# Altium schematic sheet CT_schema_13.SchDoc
size 389 x 278 mm
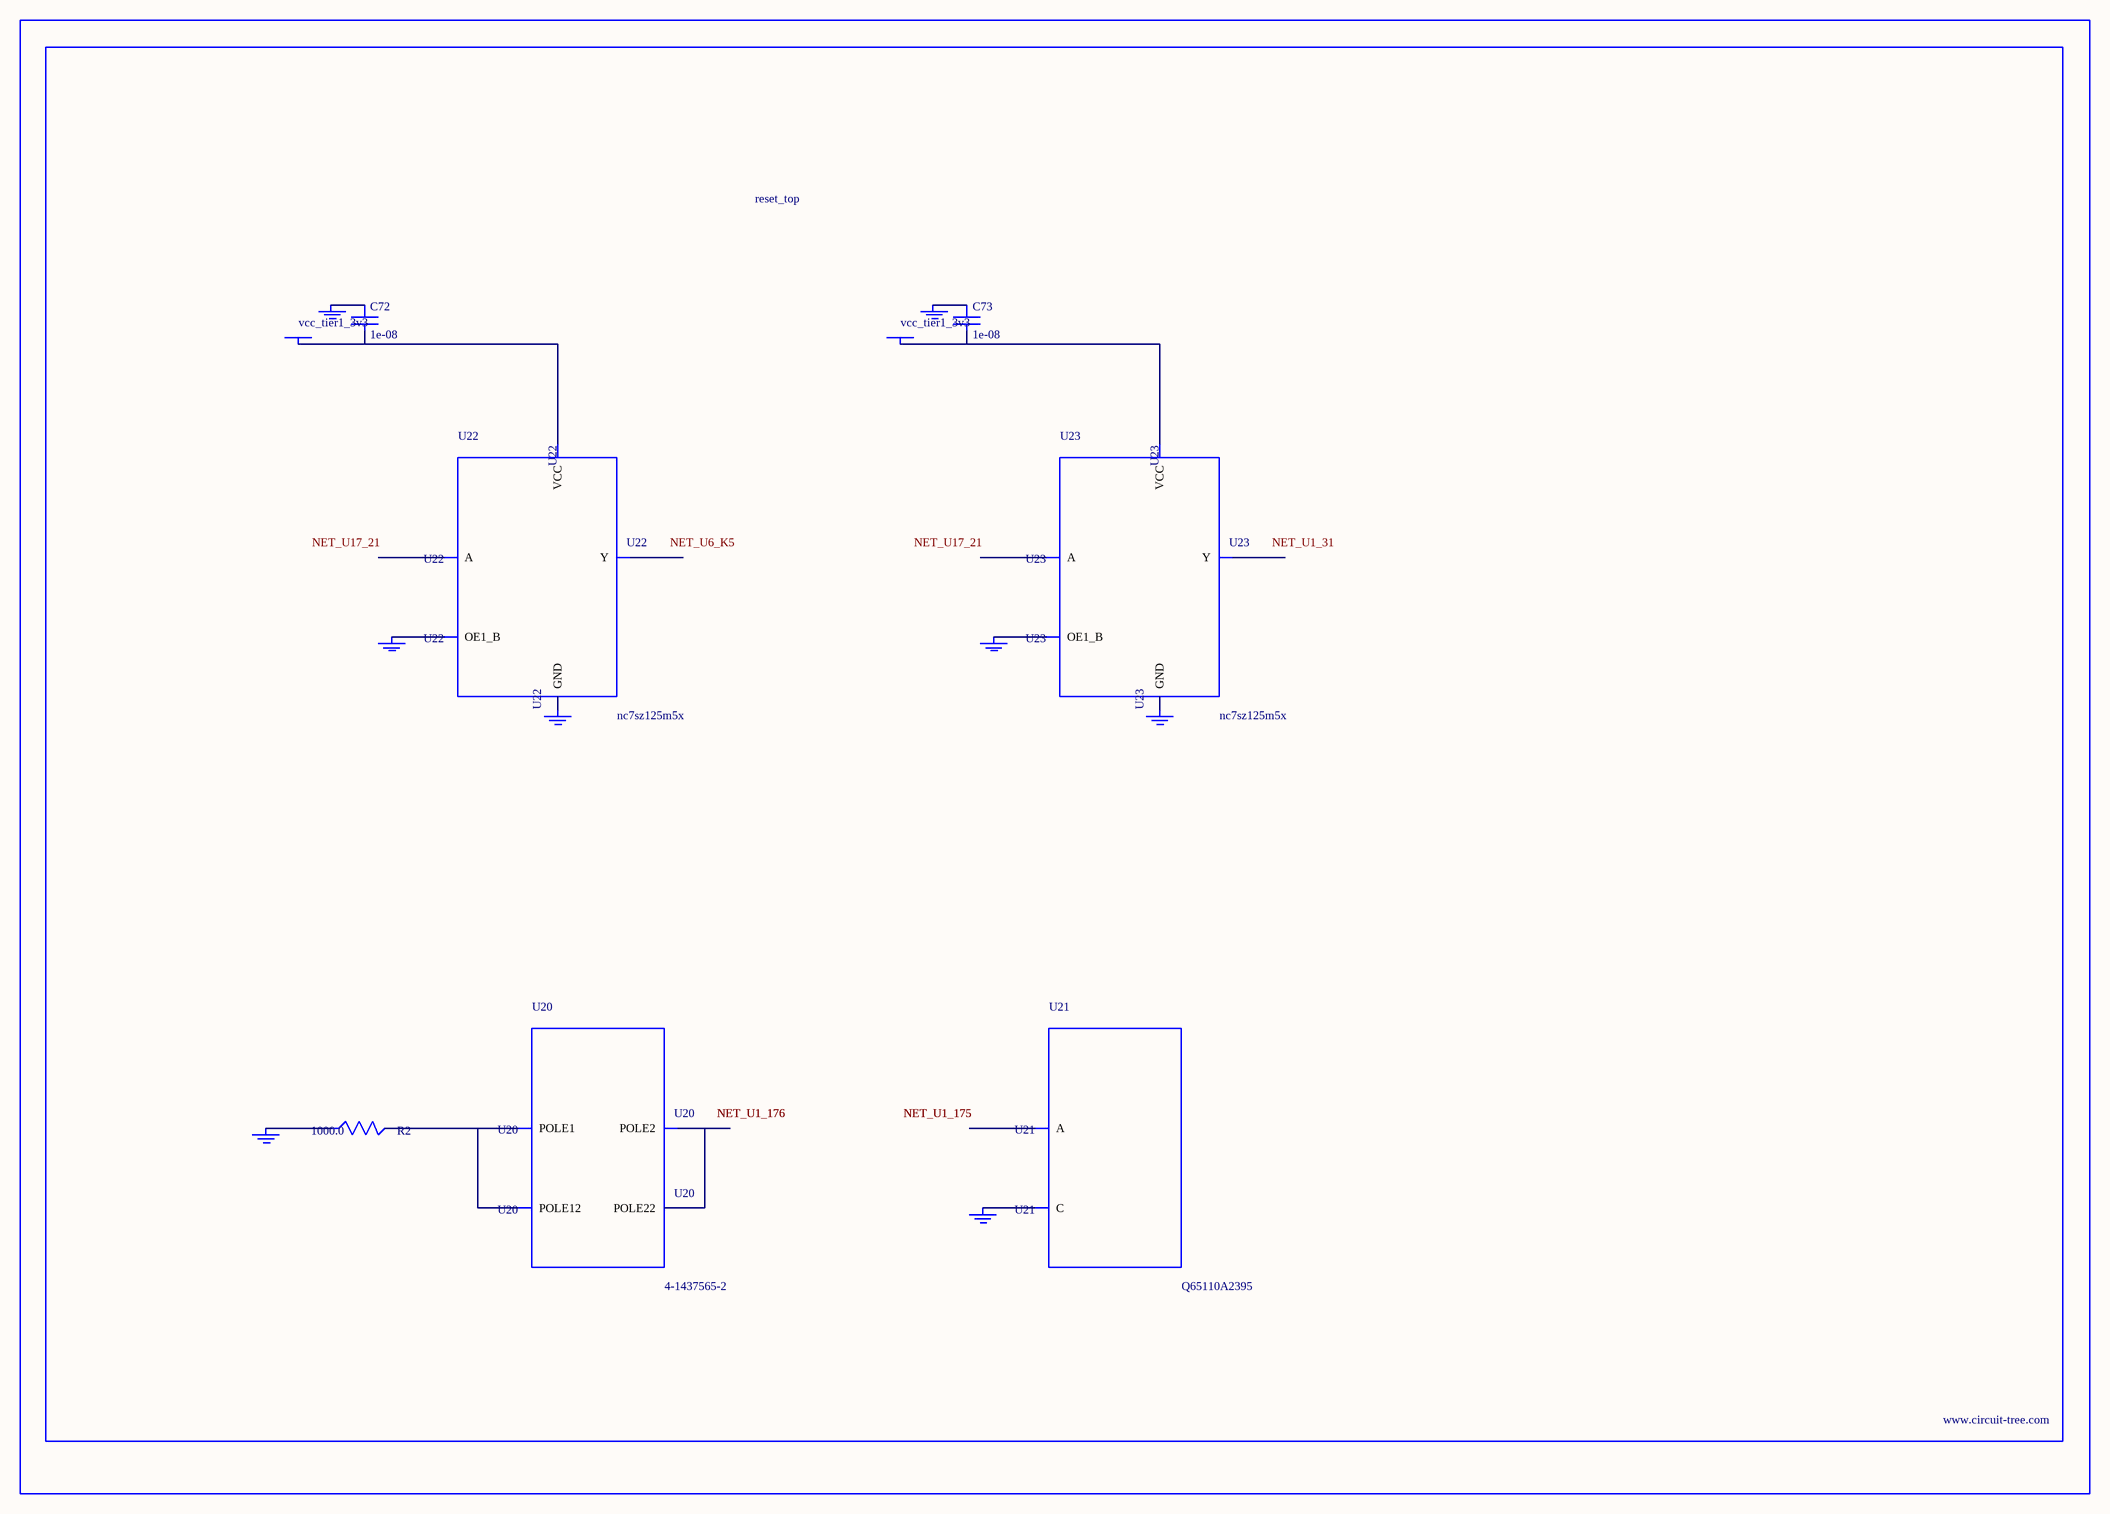
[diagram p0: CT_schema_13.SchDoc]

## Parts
BORDER12  (no value)
C72  1e-08  [C0402]
C73  1e-08  [C0402]
GND_INSTANCE_12_0  (no value)
GND_INSTANCE_12_1  (no value)
GND_INSTANCE_12_2  (no value)
GND_INSTANCE_12_3  (no value)
GND_INSTANCE_12_4  (no value)
GND_INSTANCE_12_5  (no value)
GND_INSTANCE_12_6  (no value)
GND_INSTANCE_12_7  (no value)
POWER_INSTANCE_12_0  vcc_tier1_3v3
POWER_INSTANCE_12_1  vcc_tier1_3v3
R2  1000.0  [R0603]
U20  4-1437565-2  [SW_4-1437565-2]
U21  Q65110A2395  [LGM67K-G1J2-24-Z]
U22  nc7sz125m5x  [NC7SZ125M5X]
U23  nc7sz125m5x  [NC7SZ125M5X]

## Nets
NetC72_1: C72.1 GND_INSTANCE_12_2.0(GND)
NetC72_2: C72.2 POWER_INSTANCE_12_0.0(PWR) U22.5(VCC)
NetC73_1: C73.1 GND_INSTANCE_12_5.0(GND)
NetC73_2: C73.2 POWER_INSTANCE_12_1.0(PWR) U23.5(VCC)
NetGND_INSTANCE_12_0_0: GND_INSTANCE_12_0.0(GND) R2.1
NetGND_INSTANCE_12_1_0: GND_INSTANCE_12_1.0(GND) U21.C
NetGND_INSTANCE_12_3_0: GND_INSTANCE_12_3.0(GND) U22.1(OE1_B)
NetGND_INSTANCE_12_4_0: GND_INSTANCE_12_4.0(GND) U22.3(GND)
NetGND_INSTANCE_12_6_0: GND_INSTANCE_12_6.0(GND) U23.1(OE1_B)
NetGND_INSTANCE_12_7_0: GND_INSTANCE_12_7.0(GND) U23.3(GND)
NetR2_2: R2.2 U20.1(POLE1) U20.2(POLE12)
NetU20_3: U20.3(POLE2) U20.4(POLE22)

Not connected (* = marked no-connect by the designer): U21 A; U22 2(A) 4(Y); U23 2(A) 4(Y)

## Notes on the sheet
- Labels drawn without touching a wire or pin: NET_U1_31, NET_U6_K5, NET_U17_21

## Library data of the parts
BORDER12 = BORDER_PAGE12
C72 C73 = C0402C103K3RAC
GND_INSTANCE_12_0-GND_INSTANCE_12_7 = GND
POWER_INSTANCE_12_0 POWER_INSTANCE_12_1 = PWR
R2 = RC0603JR-071KL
